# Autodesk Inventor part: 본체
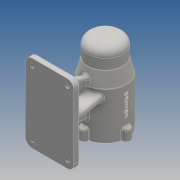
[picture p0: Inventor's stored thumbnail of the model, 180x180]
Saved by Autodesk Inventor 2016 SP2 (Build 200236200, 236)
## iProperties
Created: 2019-07
Part Number: 본체
Material: Generic
Document SubType Name: Modeling
Designer: EZ
Density: 1 g/cm^3
Appearance: Default
Mass: 238.721 g
Surface Area: 654.613 cm^2
Volume: 238.721 cm^3
Author: EZ
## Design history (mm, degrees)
sketch "스케치1"
  geometry: L1 (0, 56)-(0, -56); L2 (24, 10)-(24, -38); L3 (21, -41)-(21, -41); L4 (21, 13)-(21, 13); L5 (21, 24.7)-(21, 13); L6 (21, -41)-(21, -56); L7 (17.5, 42.7)-(17.5, 25); L8 (20.7, 25)-(17.5, 25); L9 (15.7, 47)-(10.5, 47); L10 (7.5, 50)-(0, 50); L11 (16, 46.7)-(16, 43); L12 (17.2, 43)-(16, 43); L13 (10.5, 47)-(10.5, 47); L14 (15, 56)-(0, 56); L15 (30, -56)-(21, -56); L16 (25, 46)-(25, 31); L17 (30, 11)-(25, 31); L18 (30, 11)-(30, -56); A1 r 3 centre (21, -38) between (21, -41) and (24, -38); A2 r 3 centre (21, 10) between (24, 10) and (21, 13); A3 r 0.3 centre (20.7, 24.7) between (21, 24.7) and (20.7, 25); A4 r 0.3 centre (17.2, 42.7) between (17.5, 42.7) and (17.2, 43); A5 r 0.3 centre (15.7, 46.7) between (16, 46.7) and (15.7, 47); A6 r 3 centre (7.5, 47) between (10.5, 47) and (7.5, 50); A7 r 10 centre (15, 46) between (25, 46) and (15, 56); 2 further points
  constraints: 36 end point, 14 point on circle, 14 tangent, 10 parallel, 7 centre point, 4 vertical, 3 equal radius, 3 horizontal, 1 coincident, 1 midpoint, 1 point on line
  dimensions: "d0" = 112 distance of L1.start L1.end; "d3" = 48 diameter of L2 L1; "d5" = 54 distance between parallel lines of L3 L4; "d6" = 42 diameter of L6 L1; "d7" = 42 diameter of L5 L1; "d11" = 35 diameter of L7 L1; "d13" = 3 distance between parallel lines of L9 L10; "d14" = 32 diameter of L11 L1; "d16" = 15 distance between parallel lines of L3 L15; "d17" = 6 distance between parallel lines of L14 L10; "d18" = 3 radius of A1; "d19" = 0.3 radius of A3; "d20" = 3 radius of A6; "d22" = 106 distance between parallel lines of L15 L10; "d23" = 81 distance between parallel lines of L15 L8; "d24" = 99 distance between parallel lines of L15 L12; "d28" = 50 diameter of L16 L1; "d29" = 10 radius of A7; "d30" = 25 distance from line of L16.end L14; "d31" = 45 distance from line of L17.start L14; "d32" = 60 diameter of L18 L1; "d33" = 19.5 distance between parallel lines of L13 L18
revolve "회전1" sketch "스케치1" stored, may be unused: angle "d25" = 90 deg
sketch "스케치2"
  geometry: C1 r 6 at (0, 30); 2 further points
  constraints: 2 vertical alignment, 1 centre point, 1 other
  dimensions: "d34" = 12 diameter of C1
extrude "돌출1" join sketch "스케치2" distance "d35" = 16; taper "d36" = 0 deg
fillet "모깎기1" dims "d37" = 3, "d38" = 1
hole "구멍1" diameter "d44" = 3.242; stored, may be unused: countersink angle "d48" = 90 deg, drill point angle "d50" = 118 deg; dims "d42" = 10, "d43" = 10, "d45" = 8, "d46" = 4, "d47" = 2, "d49" = 11
sketch "스케치3"
  geometry: L1 (-35, -100)-(35, -100); L2 (35, -100)-(35, -110); L3 (35, -110)-(-35, -110); L4 (-35, -110)-(-35, -100); 2 further points
  constraints: 8 end point, 2 parallel, 1 horizontal, 1 midpoint, 1 perpendicular, 1 vertical alignment
  dimensions: "d54" = 70 distance of L2.end L3.end; "d55" = 10 distance of L1.end L2.end; "d56" = 80 distance from line of point (0, -30) L3
extrude "돌출2" join sketch "스케치3" distance "d57" = 112; taper "d58" = 0 deg
sketch "스케치4"
  geometry: L1 (35, -70)-(-35, -70) reference; L2 (-19.654, -22.666)-(-28, -70); L3 (19.654, -22.666)-(28, -70); L4 (-35, -70)-(-35, -80) reference; L5 (35, -80)-(35, -70) reference; A1 r 30 centre (0, 0) between (19.654, -22.666) and (-19.654, -22.666) reference; 1 further point
  constraints: 4 end point, 2 point on circle, 2 point on line
  dimensions: "d59" = 7 distance from line of L4 L2.end; "d60" = 100 deg angle of L1 L2; "d61" = 100 deg angle of L1 L3; "d62" = 7 distance from line of L5 L3.end
extrude "돌출3" join sketch "스케치4" stored distance "d63" = 8; taper "d64" = 0 deg
sketch "스케치5"
  geometry: L1 (-70, -56)-(-70, 56) reference; L2 (-26.663, 20.226)-(-70, 36); L3 (-29, -31)-(-70, -31); L4 (-70, 56)-(-80, 56) reference; L5 (-70, -56)-(-80, -56) reference; L6 (-26.663, 20.226)-(-29, 10.877); L7 (-29, 10.877)-(-29, -31); 2 further points
  constraints: 8 end point, 2 point on line, 1 horizontal, 1 parallel
  dimensions: "d65" = 20 distance from line of L4 L2.end; "d66" = 25 distance from line of L5 L3.end; "d67" = 110 deg angle of L2 L1; "d72" = 1 distance from line of point (-30, 11) L6; "d73" = 1 distance from line of L7 point (-30, 11); "d74" = 75.9638 deg angle of L4 L6
extrude "돌출4" join sketch "스케치5" stored distance "d68" = 8; taper "d69" = 0 deg
fillet "모깎기2" dims "d75" = 10, "d76" = 3
chamfer "모따기1" distance "d77" = 3; stored, may be unused: second distance "d78" = 2, angle "d79" = 45 deg
sketch "스케치6"
  geometry: A1 r 10 centre (50, 99) between (60, 99) and (50, 109) reference; A2 r 10 centre (50, 7) between (50, -3) and (60, 7) reference; A3 r 10 centre (0, 7) between (-10, 7) and (0, -3) reference; A4 r 10 centre (0, 99) between (0, 109) and (-10, 99) reference; 1 further point
hole "구멍2" sketch "스케치6" at (50, 99), (50, 7), (0, 7), (0, 99) diameter "d80" = 6; stored, may be unused: countersink angle "d84" = 90 deg, drill point angle "d86" = 118 deg; dims "d81" = 8, "d82" = 4, "d83" = 2, "d85" = 11
node "작업 평면1"
sketch "스케치7"
  geometry: L1 (2.895, 6)-(2.895, -34); L2 (2.895, -34)-(-2.895, -34); L3 (-2.895, -34)-(-2.895, 6); L4 (-2.895, 6)-(2.895, 6); L5 (30, 10.631)-(30, -39) reference; L6 (6.771, -56)-(29.226, -56) reference; 2 further points
  constraints: 1 midpoint, 1 parallel, 1 vertical alignment, 2 other
  dimensions: "d88" = 40 distance of L1.start L1.end; "d90" = 22 distance between parallel lines of L6 L2
feature "엠보싱1" sketch "스케치7" dims "d0" = 112, "d3" = 48, "d5" = 54, "d6" = 42, "d7" = 42, "d11" = 35, "d13" = 3, "d14" = 32, "d16" = 15, "d17" = 6, "d18" = 3, "d19" = 0.3, "d20" = 3, "d22" = 106, "d23" = 81, "d24" = 99, "d28" = 50, "d29" = 10, "d30" = 25, "d31" = 45, "d32" = 60, "d33" = 19.5, "d91" = 0.5, "d92" = 0
chamfer "모따기2" distance "d93" = 1; stored, may be unused: second distance "d94" = 2, angle "d95" = 45 deg
node "솔리드1"
pattern_circular "원형 패턴2" dims "d52" = 360 deg
other parameters: "d2" = 42, "d8" = 12, "d9" = 18, "d12" = 4, "d15" = 21, "d21" = 19.5
